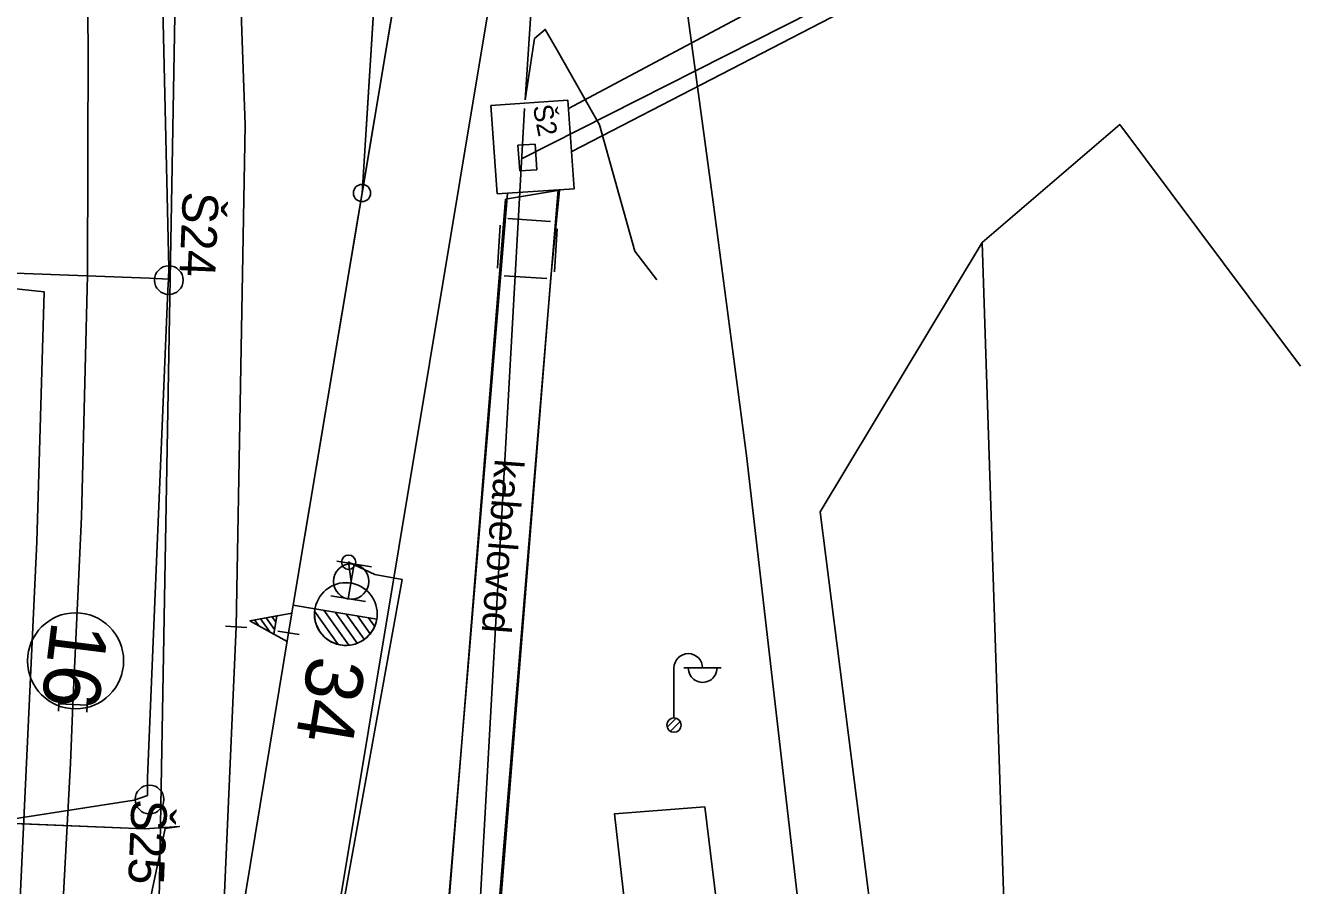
# Model space of a CAD drawing. Extents: x -545736 to -544888, y -1122892 to -1119128.
# Drawn here: x -545114.79 to -545070.2, y -1122078.04 to -1122047.96 of the extents above; entities that cross this region are included whole.
import ezdxf

# ---------------------------------------------------------------- set-up
doc = ezdxf.new("R2010")
doc.units = 0
for name, color, linetype in [('osvětlené plochy-hodnota-obrys', 7, 'Continuous'), ('Vrstva 1', 7, 'Continuous'), ('Vrstva 1 - Koleje', 7, 'Continuous'), ('Vrstva 16', 7, 'Continuous'), ('Vrstva 17', 7, 'Continuous'), ('Vrstva 2', 7, 'Continuous'), ('Vrstva 25', 7, 'Continuous'), ('Vrstva 26', 7, 'Continuous'), ('Vrstva 27', 7, 'Continuous'), ('Vrstva 28 - zabzar', 7, 'Continuous'), ('Vrstva 3', 7, 'Continuous'), ('Vrstva 3 - Lisy - Pocitaci body', 7, 'Continuous'), ('Vrstva 31', 7, 'Continuous'), ('Vrstva 34', 7, 'Continuous'), ('Vrstva 35', 7, 'Continuous'), ('Vrstva 4 - Teren - stezky - prechody - plochy', 7, 'Continuous'), ('Vrstva 43', 7, 'Continuous'), ('Vrstva 44', 7, 'Continuous'), ('Vrstva 49', 7, 'Continuous'), ('Vrstva 61', 7, 'Continuous')]:
    doc.layers.add(name, color=color, linetype=linetype)

msp = doc.modelspace()

# ---------------------------------------------------------------- linework, layer by layer
at = {"layer": 'osvětlené plochy-hodnota-obrys'}
for points in [[(-545114.36, -1122142.005), (-545095.834, -1122030.811), (-545094.039, -1122008.497), (-545094.672, -1121983.393), (-545097.737, -1121961.902), (-545099.42, -1121918.553), (-545101.285, -1121870.536), (-545123.71, -1121759.379), (-545130.296, -1121736.567), (-545147.419, -1121693.847), (-545162.352, -1121662.092), (-545176.655, -1121642.604), (-545199.404, -1121614.631), (-545212.209, -1121594.037), (-545225.557, -1121565.516)], [(-545115.194, -1122188.84), (-545115.464, -1122158.52), (-545110.116, -1122078.531), (-545109.516, -1122044.98), (-545111.654, -1121993.485), (-545115.876, -1121955.778), (-545121.955, -1121920.051), (-545160.528, -1121723.806), (-545171.589, -1121690.909), (-545189.933, -1121650.816), (-545214.916, -1121599.46)]]:
    msp.add_lwpolyline(points, dxfattribs=at)
at = {"layer": 'Vrstva 1'}
for points in [[(-545105.433, -1122068.234), (-545100.293, -1122037.549), (-545100.056, -1122036.054), (-545097.904, -1122012.428), (-545097.443, -1121999.97), (-545098.568, -1121988.313), (-545098.643, -1121987.484), (-545098.717, -1121986.607), (-545100.055, -1121970.675), (-545101.391, -1121953.551)], [(-545109.904, -1122095.374), (-545105.593, -1122069.199), (-545105.433, -1122068.234), (-545103.019, -1122053.82), (-545101.945, -1122036.704), (-545101.525, -1122017.986), (-545101.985, -1122003.523), (-545102.577, -1121994.549), (-545104.325, -1121978.003), (-545107.499, -1121957.653)], [(-545109.904, -1122095.374), (-545108.096, -1122084.399), (-545107.422, -1122068.991), (-545107.109, -1122051.446), (-545107.678, -1122035.331), (-545108.288, -1122020.588), (-545109.122, -1122000.817), (-545110.636, -1121980.411)], [(-545086.277, -1122094.6), (-545087.736, -1122078.961), (-545089.571, -1122062.994), (-545090.744, -1122054.141), (-545092.357, -1122042.208), (-545094.068, -1122029.354), (-545095.393, -1122019.621), (-545096.247, -1122012.36), (-545098.568, -1121988.313)]]:
    msp.add_lwpolyline(points, dxfattribs=at)
at = {"layer": 'Vrstva 1 - Koleje'}
msp.add_lwpolyline([(-545113.063, -1122022.444), (-545112.892, -1122031.785), (-545112.733, -1122040.009), (-545112.597, -1122048.598), (-545112.627, -1122056.692), (-545112.832, -1122065.142), (-545113.129, -1122071.707), (-545113.221, -1122073.756), (-545113.873, -1122085.957), (-545114.218, -1122092.542), (-545114.679, -1122101.258), (-545115.139, -1122110.007), (-545115.402, -1122115.122), (-545115.579, -1122118.568), (-545116.454, -1122135.101), (-545117.248, -1122150.087), (-545117.326, -1122151.565)], dxfattribs=at)
msp.add_circle((-545113.038, -1122070.18), 1.68, dxfattribs=at)
at = {"layer": 'Vrstva 17'}
msp.add_lwpolyline([(-545078.26, -1122131.126), (-545078.703, -1122122.363), (-545080.267, -1122087.807), (-545081.325, -1122055.552), (-545076.516, -1122051.421), (-545070.197, -1122059.873)], dxfattribs=at)
msp.add_lwpolyline([(-545093.483, -1122081.79), (-545090.289, -1122081.382), (-545091.032, -1122075.282), (-545094.191, -1122075.531)], close=True, dxfattribs=at)
at = {"layer": 'Vrstva 2'}
for p, q in [((-545103.019, -1122053.82), (-545101.945, -1122036.704)), ((-545104.672, -1122068.359), (-545105.433, -1122068.234)), ((-545104.68, -1122068.444), (-545103.853, -1122069.603)), ((-545104.672, -1122068.36), (-545104.671, -1122068.359)), ((-545102.507, -1122068.723), (-545104.672, -1122068.36)), ((-545104.671, -1122068.359), (-545102.507, -1122068.723)), ((-545104.357, -1122068.412), (-545103.487, -1122069.632)), ((-545103.965, -1122068.478), (-545103.192, -1122069.562)), ((-545103.572, -1122068.544), (-545102.944, -1122069.426)), ((-545107.796, -1122068.966), (-545107.048, -1122069.016)), ((-545103.18, -1122068.61), (-545102.738, -1122069.23)), ((-545102.788, -1122068.676), (-545102.58, -1122068.967)), ((-545105.963, -1122069.138), (-545105.223, -1122069.26))]:
    msp.add_line(p, q, dxfattribs=at)
msp.add_lwpolyline([(-545105.433, -1122068.234), (-545103.019, -1122053.82), (-545100.293, -1122037.549)], dxfattribs=at)
for centre, radius in [((-545103.019, -1122053.82), 0.3), ((-545103.583, -1122068.543), 1.097)]:
    msp.add_circle(centre, radius, dxfattribs=at)
msp.add_arc((-545103.589, -1122068.541), 1.098, 170.5121, 350.473, dxfattribs=at)
at = {"layer": 'Vrstva 25'}
for p, q in [((-545092.109, -1122072.176), (-545092.109, -1122070.426)), ((-545091.759, -1122070.426), (-545090.459, -1122070.426)), ((-545092.348, -1122072.499), (-545092.037, -1122072.188)), ((-545092.228, -1122072.644), (-545091.89, -1122072.306))]:
    msp.add_line(p, q, dxfattribs=at)
msp.add_circle((-545092.109, -1122072.426), 0.25, dxfattribs=at)
msp.add_circle((-545092.109, -1122072.426), 0.25, dxfattribs=at)
for centre, start, end in [((-545091.609, -1122070.426), 0, 180), ((-545091.109, -1122070.432), 179.2974, 0.7026)]:
    msp.add_arc(centre, 0.5, start, end, dxfattribs=at)
at = {"layer": 'Vrstva 26'}
for points in [[(-545097.437, -1122052.623), (-545072.287, -1122039.894), (-545085.621, -1122009.744), (-545089.841, -1121964.946), (-545095.239, -1121958.274), (-545095.745, -1121940.272), (-545098.424, -1121935.947), (-545099.088, -1121910.293), (-545099.581, -1121891.247), (-545095.82, -1121860.673), (-545104.239, -1121857.434), (-545113.591, -1121811.167), (-545113.924, -1121803.223), (-545124.359, -1121753.762), (-545132.104, -1121728.782), (-545141.308, -1121704.806), (-545150.282, -1121669.65), (-545151.919, -1121656.143), (-545151.404, -1121636.531), (-545180.167, -1121637.447), (-545212.798, -1121581.796), (-545235.977, -1121514.184), (-545242.54, -1121484.599), (-545257.211, -1121409.362)], [(-545097.311, -1122050.564), (-545097.054, -1122046.646), (-545097.053, -1122045.637), (-545096.547, -1122045.659), (-545096.69, -1122043.876)], [(-545096.341, -1122194.776), (-545098.879, -1122190.53), (-545100.126, -1122188.019), (-545101.52, -1122182.986), (-545102.161, -1122179.062), (-545101.829, -1122176.481), (-545101.954, -1122173.571), (-545103.698, -1122167.974), (-545104.535, -1122164.893), (-545105.3, -1122162.77), (-545105.412, -1122162.433), (-545107.438, -1122156.517), (-545109.168, -1122148.217), (-545110.001, -1122142.565), (-545110.562, -1122131.215), (-545109.498, -1122123.794), (-545107.074, -1122102.251), (-545102.978, -1122095.125), (-545099.549, -1122087.206), (-545099.235, -1122084.878), (-545097.339, -1122050.87)]]:
    msp.add_lwpolyline(points, dxfattribs=at)
at = {"layer": 'Vrstva 27'}
msp.add_line((-545103.486, -1122066.705), (-545103.494, -1122066.755), dxfattribs=at)
msp.add_circle((-545103.49, -1122066.73), 0.25, dxfattribs=at)
at = {"layer": 'Vrstva 28 - zabzar'}
for points in [[(-545101.25, -1122083.48), (-545102.33, -1122084.01), (-545104.56, -1122083.59), (-545101.62, -1122067.33), (-545102.57, -1122067.16), (-545103.49, -1122066.73), (-545103.4, -1122067.4)], [(-545104.03, -1122096.48), (-545106.53, -1122096.32), (-545107.17, -1122096.2), (-545107.78, -1122096.12), (-545108.55, -1122096.09), (-545111.23, -1122095.6), (-545112.02, -1122095.49), (-545111.89, -1122093.99), (-545111.38, -1122087.33), (-545110.67, -1122079.69), (-545109.9, -1122076.04), (-545109.41, -1122075.97), (-545110.62, -1122076.05), (-545116.57, -1122075.81), (-545117.45, -1122075.87), (-545119.93, -1122076.16), (-545118.79, -1122075.59), (-545117.97, -1122075.33), (-545117.45, -1122075.87)]]:
    msp.add_lwpolyline(points, dxfattribs=at)
at = {"layer": 'Vrstva 3'}
for p, q in [((-545106.778, -1122068.75), (-545106.634, -1122068.952)), ((-545106.574, -1122068.712), (-545106.249, -1122069.167)), ((-545106.371, -1122068.675), (-545106.078, -1122069.084)), ((-545106.167, -1122068.638), (-545106.035, -1122068.822))]:
    msp.add_line(p, q, dxfattribs=at)
for points in [[(-545105.477, -1122068.516), (-545106.94, -1122068.78), (-545105.641, -1122069.502)], [(-545106.105, -1122069.248), (-545105.999, -1122068.607), (-545106.94, -1122068.78), (-545106.105, -1122069.248)], [(-545106.105, -1122069.248), (-545105.999, -1122068.607)]]:
    msp.add_lwpolyline(points, dxfattribs=at)
at = {"layer": 'Vrstva 3 - Lisy - Pocitaci body'}
for p, q in [((-545102.691, -1122066.894), (-545103.906, -1122066.691)), ((-545103.298, -1122066.792), (-545103.502, -1122068.008)), ((-545102.894, -1122068.109), (-545104.109, -1122067.906)), ((-545113.617, -1122071.435), (-545113.64, -1122071.934)), ((-545112.618, -1122071.48), (-545112.641, -1122071.979)), ((-545112.63, -1122071.73), (-545113.628, -1122071.684))]:
    msp.add_line(p, q, dxfattribs=at)
msp.add_circle((-545103.4, -1122067.403), 0.616, dxfattribs=at)
at = {"layer": 'Vrstva 31'}
msp.add_lwpolyline([(-545097.311, -1122050.564), (-545096.99, -1122048.42), (-545096.61, -1122048.1), (-545096.2, -1122048.83), (-545094.71, -1122051.44), (-545093.48, -1122055.85), (-545092.71, -1122056.86)], dxfattribs=at)
at = {"layer": 'Vrstva 34'}
for p, q in [((-545097.925, -1122054.715), (-545096.428, -1122054.811)), ((-545098.287, -1122056.445), (-545098.191, -1122054.948)), ((-545096.195, -1122055.077), (-545096.291, -1122056.574)), ((-545096.557, -1122056.807), (-545098.054, -1122056.711))]:
    msp.add_line(p, q, dxfattribs=at)
at = {"layer": 'Vrstva 35'}
msp.add_line((-545116.57, -1122075.81), (-545110.62, -1122076.05), dxfattribs=at)
msp.add_lwpolyline([(-545100.231, -1122081.719), (-545098.433, -1122081.908), (-545096.412, -1122056.776), (-545096.11, -1122053.717), (-545097.997, -1122054.035)], close=True, dxfattribs=at)
at = {"layer": 'Vrstva 4 - Teren - stezky - prechody - plochy'}
msp.add_lwpolyline([(-545115.059, -1122080.221), (-545114.393, -1122066.017), (-545114.141, -1122057.271), (-545115.676, -1122057.113)], dxfattribs=at)
at = {"layer": 'Vrstva 43'}
for centre in [(-545109.777, -1122056.867), (-545110.453, -1122075.028)]:
    msp.add_circle(centre, 0.5, dxfattribs=at)
at = {"layer": 'Vrstva 44'}
for points in [[(-545145.881, -1122080.467), (-545110.994, -1122075.048), (-545110.527, -1122074.885), (-545110.524, -1122074.261), (-545109.816, -1122057.219), (-545109.784, -1122056.831), (-545109.776, -1122056.431), (-545110.644, -1122019.05), (-545110.681, -1122018.615), (-545110.652, -1122018.269), (-545112.055, -1121989.719), (-545112.056, -1121989.341), (-545112.028, -1121988.988), (-545115.846, -1121954.609), (-545115.954, -1121954.18), (-545116.046, -1121953.82), (-545122.306, -1121918.54), (-545122.337, -1121918.274), (-545121.996, -1121918.289), (-545097.226, -1121913.425), (-545096.722, -1121913.307), (-545096.631, -1121912.848), (-545094.158, -1121900.041)], [(-545117.773, -1122114.404), (-545115.421, -1122056.969), (-545115.407, -1122056.634), (-545115.153, -1122056.619), (-545110.45, -1122056.795), (-545109.784, -1122056.831)]]:
    msp.add_lwpolyline(points, dxfattribs=at)
at = {"layer": 'Vrstva 49'}
for p, q in [((-545095.8, -1122050.866), (-545074.411, -1122039.464)), ((-545095.687, -1122052.371), (-545073.75, -1122041.03)), ((-545095.82, -1122050.575), (-545098.514, -1122050.762)), ((-545095.82, -1122050.575), (-545095.606, -1122053.668)), ((-545098.514, -1122050.762), (-545098.299, -1122053.854)), ((-545097.565, -1122052.149), (-545096.967, -1122052.108)), ((-545097.565, -1122052.149), (-545097.503, -1122053.047)), ((-545096.967, -1122052.108), (-545096.905, -1122053.006)), ((-545097.503, -1122053.047), (-545096.905, -1122053.006)), ((-545100.261, -1122081.789), (-545097.931, -1122053.829)), ((-545096.159, -1122053.706), (-545098.5, -1122081.932)), ((-545095.606, -1122053.668), (-545098.299, -1122053.854))]:
    msp.add_line(p, q, dxfattribs=at)
msp.add_lwpolyline([(-545078.26, -1122131.126), (-545081.312, -1122130.085), (-545081.943, -1122122.513), (-545084.018, -1122088.394), (-545086.999, -1122064.967), (-545081.325, -1122055.552)], dxfattribs=at)

# ---------------------------------------------------------------- texts
at = {"layer": 'Vrstva 1 - Koleje'}
msp.add_text('16', height=2, rotation=262.9295, dxfattribs=at).set_placement((-545113.868, -1122068.745))
at = {"layer": 'Vrstva 16'}
msp.add_text('kabelovod', height=1, rotation=265.6546, dxfattribs=at).set_placement((-545098.373, -1122063.097))
at = {"layer": 'Vrstva 2'}
msp.add_text('34', height=2, rotation=260.6495, dxfattribs=at).set_placement((-545104.858, -1122069.941))
at = {"layer": 'Vrstva 43'}
for s, p in [('Š24', (-545109.282, -1122053.754)), ('Š25', (-545111.077, -1122075.002))]:
    msp.add_text(s, height=1.25, rotation=267.621, dxfattribs=at).set_placement(p)
at = {"layer": 'Vrstva 61'}
msp.add_text('Š2', height=0.6806, rotation=281.0281, dxfattribs=at).set_placement((-545097.053, -1122050.791))

doc.saveas('drawing.dxf')
